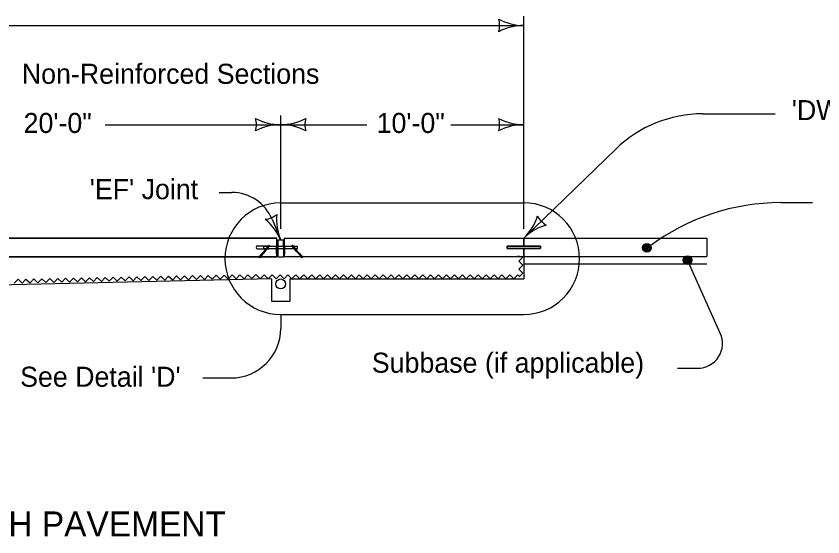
# Model space of a CAD drawing. Extents: x 9234 to 81668, y 5635 to 15999.
# Drawn here: x 15084 to 15729, y 8976 to 9392 of the extents above; entities that cross this region are included whole.
import ezdxf

# ---------------------------------------------------------------- set-up
doc = ezdxf.new("R2010")
doc.units = 0
for name, color, linetype in [('PS_BOLT', 7, 'Continuous'), ('PS_CONST', 7, 'Continuous'), ('PS_DAWA', 7, 'Continuous'), ('PS_DIM', 7, 'Continuous'), ('PS_SHAPE', 7, 'Continuous')]:
    doc.layers.add(name, color=color, linetype=linetype)

msp = doc.modelspace()

# ---------------------------------------------------------------- linework, layer by layer
at = {"layer": 'PS_BOLT'}
for p, q in [((15299.32, 9214.56), (15490.28, 9214.6)), ((15490.28, 9214.6), (15490.29, 9214.64)), ((15490.28, 9214.6), (15490.28, 9208.11)), ((15490.28, 9208.11), (15490.28, 9214.6)), ((15490.29, 9214.64), (15490.29, 9208.15)), ((15298.9, 9214.14), (15298.9, 9214.14)), ((15298.9, 9199.7), (15298.9, 9214.14)), ((15490.29, 9208.15), (15476.92, 9208.14)), ((15476.92, 9208.14), (15476.92, 9206.28)), ((15490.28, 9208.11), (15476.92, 9208.1)), ((15476.92, 9208.1), (15490.28, 9208.11)), ((15476.92, 9208.1), (15476.92, 9206.24)), ((15503.65, 9208.1), (15476.92, 9208.1)), ((15476.92, 9206.29), (15490.29, 9206.29)), ((15476.92, 9206.24), (15490.26, 9206.25)), ((15490.26, 9206.25), (15490.28, 9199.75)), ((15490.28, 9199.75), (15490.26, 9206.25)), ((15490.28, 9206.21), (15503.65, 9206.25)), ((15490.29, 9206.29), (15490.29, 9199.79)), ((15503.65, 9206.24), (15503.65, 9208.1)), ((15590.92, 9208.08), (15589.93, 9207.34)), ((15386.49, 9199.71), (15298.9, 9199.71)), ((15490.28, 9199.75), (15386.49, 9199.7)), ((15490.29, 9199.79), (15490.28, 9199.75))]:
    msp.add_line(p, q, dxfattribs=at)
msp.add_lwpolyline([(15298.9, 9214.14), (15298.99, 9214.48), (15299.32, 9214.56)], dxfattribs=at)
at = {"layer": 'PS_CONST'}
for p, q in [((15633.27, 9313.78), (15691.16, 9313.78)), ((15490.29, 9214.6), (15563.74, 9285.65)), ((15246.66, 9250.95), (15257, 9250.95)), ((15295.93, 9242.65), (15490.29, 9242.69)), ((15695.63, 9242.86), (15720.96, 9242.86)), ((15289, 9229.61), (15295.93, 9212.95)), ((15647.31, 9138.53), (15621.07, 9196.83)), ((15295.93, 9153.55), (15490.29, 9153.59)), ((15295.93, 9153.55), (15295.93, 9142.45)), ((15613.03, 9110.61), (15629.27, 9110.61)), ((15233.69, 9102.85), (15256.33, 9102.85))]:
    msp.add_line(p, q, dxfattribs=at)
for points in [[(15588.41, 9203.52), (15589.57, 9204.05), (15591.39, 9204.61), (15591.74, 9206.46), (15591.5, 9208.08), (15590.33, 9209.57), (15588.6, 9209.42), (15586.77, 9209.16), (15585.9, 9207.71), (15585.74, 9206.18), (15586.81, 9204.17), (15588.14, 9204), (15589.97, 9204.47), (15591.46, 9205.63), (15591.41, 9207.36), (15590.25, 9208.75), (15588.62, 9208.91), (15586.79, 9208.55), (15586.51, 9207.52), (15586.15, 9206.29), (15587, 9204.78), (15588.33, 9204.82), (15589.85, 9205.07), (15590.94, 9205.92), (15590.39, 9207.43), (15589.25, 9208.32), (15587.71, 9208.37), (15587.33, 9207.55), (15586.85, 9206.62), (15587.6, 9205.42), (15588.72, 9205.14), (15589.73, 9205.68), (15589.8, 9206.8), (15589.27, 9207.6), (15588.24, 9207.88), (15587.74, 9207.46), (15587.45, 9206.84), (15587.99, 9205.94), (15588.71, 9205.75), (15589.41, 9206.18), (15589.29, 9206.79), (15588.77, 9207.18), (15588.06, 9207.16), (15588.07, 9206.65), (15588.69, 9206.36)], [(15620.8, 9193.65), (15621.97, 9194.18), (15623.79, 9194.74), (15624.14, 9196.59), (15623.89, 9198.21), (15622.73, 9199.71), (15621, 9199.55), (15619.18, 9199.3), (15618.3, 9197.85), (15618.14, 9196.31), (15619.22, 9194.31), (15620.55, 9194.14), (15622.37, 9194.6), (15623.86, 9195.76), (15623.81, 9197.49), (15622.65, 9198.89), (15621.01, 9199.04), (15619.19, 9198.69), (15618.91, 9197.66), (15618.54, 9196.43), (15619.4, 9194.92), (15620.73, 9194.96), (15622.25, 9195.21), (15623.34, 9196.06), (15622.79, 9197.57), (15621.64, 9198.45), (15620.11, 9198.51), (15619.73, 9197.68), (15619.25, 9196.75), (15620, 9195.55), (15621.12, 9195.28), (15622.13, 9195.81), (15622.2, 9196.94), (15621.66, 9197.74), (15620.64, 9198.01), (15620.14, 9197.59), (15619.85, 9196.97), (15620.39, 9196.07), (15621.11, 9195.89), (15621.8, 9196.32), (15621.69, 9196.92), (15621.17, 9197.32), (15620.45, 9197.29), (15620.47, 9196.78), (15621.09, 9196.5)]]:
    msp.add_lwpolyline(points, dxfattribs=at)
for centre in [(15588.68, 9206.7), (15621.07, 9196.83)]:
    msp.add_circle(centre, 3.47, dxfattribs=at)
for centre, radius, start, end in [((15633.27, 9213.78), 100, 90, 134.0496), ((15257.01, 9216.3), 34.65, 22.59071, 90), ((15295.93, 9198.1), 44.55, 90, 270), ((15490.29, 9198.14), 44.55, 270, 90), ((15695.63, 9067.86), 175, 90, 126.74873), ((15282.16, 9246.05), 16.51, 274.85846, 310.32516), ((15256.46, 9196.53), 42.75, 22.59181, 50.6643), ((15335.4, 9229.37), 42.75, 174.51932, 202.59181), ((15460.56, 9245.32), 42.75, 314.04979, 342.12228), ((15516.05, 9239.52), 16.51, 206.31644, 241.78314), ((15520.01, 9183.87), 42.75, 105.97731, 134.04979), ((15256.33, 9142.45), 39.6, 270, 360), ((15629.27, 9130.41), 19.8, 270, 24.23803)]:
    msp.add_arc(centre, radius, start, end, dxfattribs=at)
at = {"layer": 'PS_DAWA'}
for p, q in [((15490.29, 9222.02), (15490.29, 9391.79)), ((14137.63, 9384.31), (15490.29, 9384.36)), ((15295.93, 9221.98), (15295.93, 9312.54)), ((15155.6, 9305.11), (15295.93, 9305.11)), ((15295.93, 9305.11), (15364.7, 9305.11)), ((15431.8, 9305.11), (15490.28, 9305.11))]:
    msp.add_line(p, q, dxfattribs=at)
for centre, radius, start, end in [((15454.44, 9384.36), 16.51, 342.26665, 17.73335), ((15490.29, 9427.11), 42.75, 241.92751, 270), ((15490.29, 9341.61), 42.75, 90, 118.07249), ((15260.09, 9305.12), 16.51, 342.26665, 17.73335), ((15295.93, 9347.87), 42.75, 241.92751, 270), ((15295.93, 9262.37), 42.75, 90, 118.07249), ((15295.93, 9347.87), 42.75, 270, 298.07249), ((15295.93, 9262.37), 42.75, 61.92751, 90), ((15331.77, 9305.12), 16.51, 162.26665, 197.73335), ((15454.44, 9305.12), 16.51, 342.26665, 17.73335), ((15490.28, 9347.87), 42.75, 241.92751, 270), ((15490.28, 9262.37), 42.75, 90, 118.07249)]:
    msp.add_arc(centre, radius, start, end, dxfattribs=at)
at = {"layer": 'PS_DIM'}
for p, q in [((15299.31, 9214.56), (15490.29, 9214.6)), ((15490.29, 9214.6), (15490.29, 9208.1)), ((15490.29, 9214.6), (15636.47, 9214.6)), ((15636.47, 9214.6), (15636.47, 9199.75)), ((14137.63, 9214.56), (15292.54, 9214.56)), ((15292.54, 9214.56), (14939.52, 9214.56)), ((15277.52, 9208.32), (15286.08, 9208.32)), ((15286.32, 9208.61), (15282.64, 9204.22)), ((15283.57, 9204.22), (15286.87, 9208.15)), ((15292.78, 9208.2), (15292.78, 9208.2)), ((15292.95, 9208.04), (15292.96, 9214.14)), ((15292.96, 9204.22), (15292.96, 9214.14)), ((15293.02, 9212.95), (15293.02, 9204.22)), ((15293.08, 9212.95), (15293.08, 9204.22)), ((15293.13, 9212.95), (15293.13, 9204.22)), ((15293.2, 9212.95), (15293.2, 9204.22)), ((15293.25, 9212.95), (15293.25, 9204.22)), ((15293.32, 9212.95), (15293.32, 9204.22)), ((15293.37, 9212.95), (15293.37, 9204.22)), ((15293.44, 9212.95), (15293.44, 9204.22)), ((15293.49, 9212.95), (15293.49, 9204.22)), ((15293.55, 9212.95), (15293.55, 9208.02)), ((15298.31, 9212.95), (15293.55, 9212.95)), ((15293.55, 9212.95), (15293.55, 9208.02)), ((15298.31, 9212.95), (15298.31, 9208.02)), ((15298.31, 9208.02), (15298.31, 9212.95)), ((15298.36, 9212.95), (15298.36, 9204.22)), ((15298.43, 9212.95), (15298.43, 9204.22)), ((15298.48, 9212.95), (15298.48, 9204.22)), ((15298.54, 9212.95), (15298.54, 9204.22)), ((15298.6, 9212.95), (15298.6, 9204.22)), ((15298.66, 9212.95), (15298.66, 9204.22)), ((15298.72, 9212.95), (15298.72, 9204.22)), ((15298.78, 9212.95), (15298.78, 9204.22)), ((15298.84, 9212.95), (15298.84, 9204.22)), ((15298.9, 9204.22), (15298.9, 9214.14)), ((15308.29, 9204.22), (15304.99, 9208.15)), ((15305.54, 9208.61), (15309.22, 9204.22)), ((15277.52, 9205.94), (15284.09, 9205.94)), ((15280.89, 9202.13), (15278.47, 9199.25)), ((15281.82, 9202.13), (15279.02, 9198.79)), ((15282.64, 9204.22), (15280.89, 9202.13)), ((15283.57, 9204.22), (15281.82, 9202.13)), ((15282.56, 9206.24), (15282.56, 9208.02)), ((15282.56, 9208.02), (15285.83, 9208.02)), ((15282.56, 9206.24), (15284.34, 9206.24)), ((15285.02, 9205.94), (15286.43, 9205.94)), ((15285.27, 9206.24), (15292.6, 9206.24)), ((15285.83, 9208.02), (15285.83, 9208.02)), ((15286.43, 9206.24), (15286.43, 9205.94)), ((15286.76, 9208.02), (15292.6, 9208.02)), ((15292.6, 9202.08), (15292.6, 9208.02)), ((15292.6, 9202.08), (15292.6, 9208.02)), ((15292.6, 9202.08), (15292.6, 9202.08)), ((15292.95, 9199.71), (15292.96, 9202.08)), ((15292.96, 9202.13), (15292.96, 9204.22)), ((15292.96, 9199.71), (15292.96, 9202.13)), ((15293.02, 9204.22), (15293.02, 9202.13)), ((15293.02, 9202.13), (15293.02, 9199.71)), ((15293.08, 9204.22), (15293.08, 9202.13)), ((15293.08, 9202.13), (15293.08, 9199.71)), ((15293.13, 9204.22), (15293.13, 9202.13)), ((15293.13, 9202.13), (15293.13, 9199.71)), ((15293.2, 9204.22), (15293.2, 9202.13)), ((15293.2, 9202.13), (15293.2, 9199.71)), ((15293.25, 9204.22), (15293.25, 9202.13)), ((15293.25, 9202.13), (15293.25, 9199.71)), ((15293.32, 9204.22), (15293.32, 9202.13)), ((15293.32, 9202.13), (15293.32, 9199.71)), ((15293.37, 9204.22), (15293.37, 9202.13)), ((15293.37, 9202.13), (15293.37, 9199.71)), ((15293.44, 9204.22), (15293.44, 9202.13)), ((15293.44, 9202.13), (15293.44, 9199.71)), ((15293.49, 9204.22), (15293.49, 9202.13)), ((15293.49, 9202.13), (15293.49, 9199.71)), ((15293.55, 9208.02), (15293.55, 9206.24)), ((15293.55, 9208.02), (15298.31, 9208.02)), ((15293.55, 9206.24), (15298.31, 9206.24)), ((15293.55, 9206.24), (15293.55, 9204.22)), ((15293.55, 9204.22), (15293.55, 9202.13)), ((15293.55, 9202.13), (15293.55, 9199.71)), ((15298.31, 9208.02), (15298.31, 9206.24)), ((15298.31, 9206.24), (15298.31, 9204.22)), ((15298.31, 9204.22), (15298.31, 9202.13)), ((15298.31, 9202.13), (15298.31, 9199.71)), ((15298.36, 9204.22), (15298.36, 9202.13)), ((15298.36, 9202.13), (15298.36, 9199.71)), ((15298.43, 9204.22), (15298.43, 9202.13)), ((15298.43, 9202.13), (15298.43, 9199.71)), ((15298.48, 9204.22), (15298.48, 9202.13)), ((15298.48, 9202.13), (15298.48, 9199.71)), ((15298.54, 9204.22), (15298.54, 9202.13)), ((15298.54, 9202.13), (15298.54, 9199.71)), ((15298.6, 9204.22), (15298.6, 9202.13)), ((15298.6, 9202.13), (15298.6, 9199.71)), ((15298.66, 9204.22), (15298.66, 9202.13)), ((15298.66, 9202.13), (15298.66, 9199.71)), ((15298.72, 9204.22), (15298.72, 9202.13)), ((15298.72, 9202.13), (15298.72, 9199.71)), ((15298.78, 9204.22), (15298.78, 9202.13)), ((15298.78, 9202.13), (15298.78, 9199.71)), ((15298.84, 9204.22), (15298.84, 9202.13)), ((15298.84, 9202.13), (15298.84, 9199.71)), ((15298.9, 9202.13), (15298.9, 9204.22)), ((15298.9, 9199.71), (15298.9, 9202.13)), ((15299.26, 9202.08), (15299.26, 9208.02)), ((15299.26, 9208.02), (15305.09, 9208.02)), ((15299.26, 9207.78), (15299.26, 9207.78)), ((15299.26, 9206.24), (15306.59, 9206.24)), ((15306.03, 9208.02), (15306.03, 9208.02)), ((15306.03, 9208.02), (15309.29, 9208.02)), ((15307.52, 9206.24), (15309.29, 9206.24)), ((15308.29, 9204.22), (15310.04, 9202.13)), ((15309.22, 9204.22), (15310.97, 9202.13)), ((15309.29, 9206.24), (15309.29, 9208.02)), ((15310.04, 9202.13), (15312.84, 9198.79)), ((15310.97, 9202.13), (15313.39, 9199.25)), ((15476.92, 9206.24), (15476.92, 9208.1)), ((15476.92, 9208.1), (15503.65, 9208.1)), ((15503.65, 9206.24), (15476.92, 9206.24)), ((15490.29, 9206.24), (15490.29, 9199.75)), ((15503.65, 9208.1), (15503.65, 9206.24)), ((15278.86, 9199.71), (14478.47, 9199.71)), ((14939.52, 9199.71), (15278.85, 9199.71)), ((15279.02, 9198.79), (15278.47, 9199.25)), ((15278.85, 9199.71), (15292.95, 9199.71)), ((15292.96, 9199.71), (15279.78, 9199.71)), ((15293.55, 9199.71), (15298.31, 9199.71)), ((15298.31, 9199.71), (15490.29, 9199.75)), ((15312.84, 9198.79), (15313.39, 9199.25)), ((15490.29, 9199.75), (15490.29, 9181.93)), ((15490.29, 9199.75), (15636.47, 9199.75)), ((15636.47, 9193.81), (15490.29, 9193.81)), ((15288.5, 9181.89), (14171.27, 9156.64)), ((15288.5, 9181.89), (15288.5, 9164.07)), ((15303.35, 9181.89), (15490.29, 9181.93)), ((15303.35, 9181.89), (15303.35, 9164.07)), ((15288.5, 9164.07), (15303.35, 9164.07))]:
    msp.add_line(p, q, dxfattribs=at)
msp.add_lwpolyline([(15293.55, 9206.14), (15293.65, 9206.24)], dxfattribs=at)
for centre, radius in [((15283.58, 9205.7), 0.238), ((15308.03, 9206), 0.238), ((15278.74, 9199.94), 0.238), ((15313.12, 9199.94), 0.238), ((15295.93, 9177.93), 3.96)]:
    msp.add_circle(centre, radius, dxfattribs=at)
for centre, radius, start, end in [((15277.52, 9207.13), 1.19, 90, 270), ((15286.6, 9208.38), 0.356, 320.00367, 139.99636), ((15292.54, 9214.14), 0.416, 360, 90), ((15292.55, 9214.14), 0.416, 0, 90), ((15292.78, 9208.02), 0.178, 5.43269, 180), ((15292.78, 9208.02), 0.178, 0, 180), ((15299.32, 9214.14), 0.416, 90, 180), ((15299.08, 9208.02), 0.178, 0, 180), ((15305.26, 9208.38), 0.356, 40.00364, 219.99633), ((15292.78, 9202.08), 0.178, 180, 359.93724), ((15292.78, 9202.08), 0.178, 180, 0), ((15299.08, 9202.08), 0.178, 180, 0)]:
    msp.add_arc(centre, radius, start, end, dxfattribs=at)
for points in [[(15299.26, 9207.9), (15299.29, 9207.9), (15299.32, 9207.9), (15299.34, 9207.9), (15299.36, 9207.9), (15299.38, 9207.9), (15299.4, 9207.9)], [(15299.26, 9207.78), (15299.29, 9207.78), (15299.32, 9207.78), (15299.34, 9207.78), (15299.36, 9207.78), (15299.38, 9207.78), (15299.4, 9207.78)], [(15299.26, 9207.66), (15299.29, 9207.66), (15299.32, 9207.66), (15299.34, 9207.66), (15299.36, 9207.66), (15299.38, 9207.66), (15299.4, 9207.66)], [(15299.26, 9207.55), (15299.29, 9207.54), (15299.32, 9207.55), (15299.34, 9207.55), (15299.36, 9207.55), (15299.38, 9207.54), (15299.4, 9207.55)], [(15299.26, 9207.43), (15299.29, 9207.42), (15299.32, 9207.43), (15299.34, 9207.43), (15299.36, 9207.43), (15299.38, 9207.42), (15299.4, 9207.43)], [(15299.26, 9207.31), (15299.29, 9207.3), (15299.32, 9207.31), (15299.34, 9207.31), (15299.36, 9207.31), (15299.38, 9207.3), (15299.4, 9207.31)], [(15299.26, 9207.19), (15299.29, 9207.19), (15299.32, 9207.19), (15299.34, 9207.19), (15299.36, 9207.19), (15299.38, 9207.19), (15299.4, 9207.19)], [(15299.26, 9207.07), (15299.29, 9207.07), (15299.32, 9207.07), (15299.34, 9207.07), (15299.36, 9207.07), (15299.38, 9207.07), (15299.4, 9207.07)], [(15299.26, 9206.95), (15299.29, 9206.95), (15299.32, 9206.95), (15299.34, 9206.95), (15299.36, 9206.95), (15299.38, 9206.95), (15299.4, 9206.95)], [(15299.26, 9206.83), (15299.29, 9206.83), (15299.32, 9206.83), (15299.34, 9206.83), (15299.36, 9206.83), (15299.38, 9206.83), (15299.4, 9206.83)], [(15299.26, 9206.71), (15299.29, 9206.71), (15299.32, 9206.71), (15299.34, 9206.71), (15299.36, 9206.71), (15299.38, 9206.71), (15299.4, 9206.71)], [(15299.26, 9206.6), (15299.29, 9206.59), (15299.32, 9206.6), (15299.34, 9206.6), (15299.36, 9206.6), (15299.38, 9206.59), (15299.4, 9206.6)], [(15299.26, 9206.48), (15299.29, 9206.47), (15299.32, 9206.48), (15299.34, 9206.48), (15299.36, 9206.48), (15299.38, 9206.47), (15299.4, 9206.48)], [(15299.26, 9206.36), (15299.29, 9206.35), (15299.32, 9206.36), (15299.34, 9206.36), (15299.36, 9206.36), (15299.38, 9206.35), (15299.4, 9206.36)]]:
    msp.add_spline(points, degree=3, dxfattribs=at)
at = {"layer": 'PS_SHAPE'}
for p, q in [((15292.96, 9212.95), (15293.55, 9212.95)), ((15298.31, 9212.95), (15298.9, 9212.95)), ((15486.94, 9199.75), (15485.03, 9199.75))]:
    msp.add_line(p, q, dxfattribs=at)
for points in [[(15293.55, 9212.9), (15293.6, 9212.95)], [(15486.65, 9183.74), (15489.56, 9186.65), (15486.39, 9189.81), (15489.55, 9192.98), (15486.38, 9196.15), (15489.55, 9199.32), (15489.12, 9199.75)], [(15082.9, 9178.43), (15086, 9181.66), (15089.24, 9178.57), (15092.34, 9181.8), (15095.57, 9178.7), (15098.67, 9181.94), (15101.91, 9178.84), (15105.01, 9182.07), (15108.24, 9178.97), (15111.34, 9182.21), (15114.58, 9179.11), (15117.67, 9182.35), (15120.91, 9179.24), (15124.01, 9182.48), (15125.63, 9180.93)], [(15125.63, 9180.93), (15127.24, 9179.38), (15130.35, 9182.61), (15133.58, 9179.51), (15136.68, 9182.75), (15139.91, 9179.65), (15143.01, 9182.88), (15146.25, 9179.79), (15149.35, 9183.02), (15152.58, 9179.92), (15155.68, 9183.16), (15158.91, 9180.06), (15162.02, 9183.29), (15165.25, 9180.19), (15168.35, 9183.43), (15171.59, 9180.33), (15174.69, 9183.56), (15177.92, 9180.46), (15181.02, 9183.7), (15184.26, 9180.6), (15187.36, 9183.83), (15190.59, 9180.73), (15193.69, 9183.97), (15196.92, 9180.87), (15200.03, 9184.1), (15201.64, 9182.55)], [(15201.64, 9182.55), (15203.26, 9181), (15206.37, 9184.22), (15209.59, 9181.11), (15212.7, 9184.33), (15215.93, 9181.22), (15219.04, 9184.44), (15222.26, 9181.33), (15225.37, 9184.55), (15228.6, 9181.44), (15231.71, 9184.66), (15234.93, 9181.55), (15238.04, 9184.77), (15241.27, 9181.66), (15244.38, 9184.88), (15247.6, 9181.77), (15250.71, 9184.99), (15253.94, 9181.88), (15257.05, 9185.1), (15260.27, 9181.99), (15263.38, 9185.21), (15266.61, 9182.1), (15269.72, 9185.33), (15272.94, 9182.21), (15276.05, 9185.44), (15277.99, 9183.56)], [(15277.99, 9183.56), (15279.57, 9181.98), (15282.74, 9185.15), (15285.91, 9181.98), (15289.08, 9185.15), (15292.25, 9181.98), (15295.41, 9185.15), (15298.58, 9181.99), (15301.75, 9185.15), (15304.92, 9181.99), (15308.09, 9185.16), (15311.25, 9181.99), (15314.42, 9185.16), (15317.59, 9181.99), (15320.76, 9185.16), (15323.93, 9182), (15327.09, 9185.17), (15330.26, 9182), (15333.43, 9185.17), (15336.6, 9182), (15339.77, 9185.17), (15342.93, 9182.01), (15346.1, 9185.17), (15349.27, 9182.01), (15352.44, 9185.17), (15354.02, 9183.59)], [(15354.02, 9183.59), (15355.61, 9182.01), (15358.77, 9185.18), (15361.94, 9182.01), (15365.11, 9185.18), (15368.28, 9182.01), (15371.45, 9185.18), (15374.61, 9182.01), (15377.78, 9185.18), (15380.95, 9182.02), (15384.12, 9185.19), (15387.29, 9182.02), (15390.45, 9185.19), (15393.62, 9182.02), (15396.79, 9185.19), (15399.96, 9182.03), (15403.13, 9185.19), (15406.29, 9182.03), (15409.46, 9185.19), (15412.63, 9182.03), (15415.8, 9185.2), (15418.97, 9182.03), (15422.13, 9185.2), (15425.3, 9182.03), (15428.47, 9185.2), (15430.05, 9183.62)], [(15430.05, 9183.62), (15431.64, 9182.03), (15434.81, 9185.21), (15437.97, 9182.04), (15441.14, 9185.21), (15444.31, 9182.04), (15447.48, 9185.21), (15450.65, 9182.04), (15453.81, 9185.21), (15456.98, 9182.05), (15460.15, 9185.21), (15463.32, 9182.05), (15466.49, 9185.21), (15469.65, 9182.05), (15472.82, 9185.22), (15475.99, 9182.05), (15479.16, 9185.22), (15482.33, 9182.05), (15485.49, 9185.22), (15486.81, 9183.9)]]:
    msp.add_lwpolyline(points, dxfattribs=at)

# ---------------------------------------------------------------- texts
at = {"layer": 'PS_BOLT'}
msp.add_text('SECTION THRU CENTERLINE - EAST APPROACH PAVEMENT', height=20, dxfattribs=at).set_placement((14469.01, 8976.26))
at = {"layer": 'PS_CONST'}
for s, p in [("'DW' or 'RT' Joint", (15704.46, 9308.75)), ("'EF' Joint", (15143.31, 9245.61)), ('Subbase (if applicable)', (15368.76, 9107.05)), ("See Detail 'D'", (15087.65, 9095.84))]:
    msp.add_text(s, height=16, dxfattribs=at).set_placement(p)
at = {"layer": 'PS_DAWA'}
for s, p in [('Non-Reinforced Sections', (15089.01, 9337.76)), ('20\'-0"', (15090.43, 9298.48)), ('10\'-0"', (15372.6, 9298.48))]:
    msp.add_text(s, height=16, dxfattribs=at).set_placement(p)

doc.saveas('drawing.dxf')
